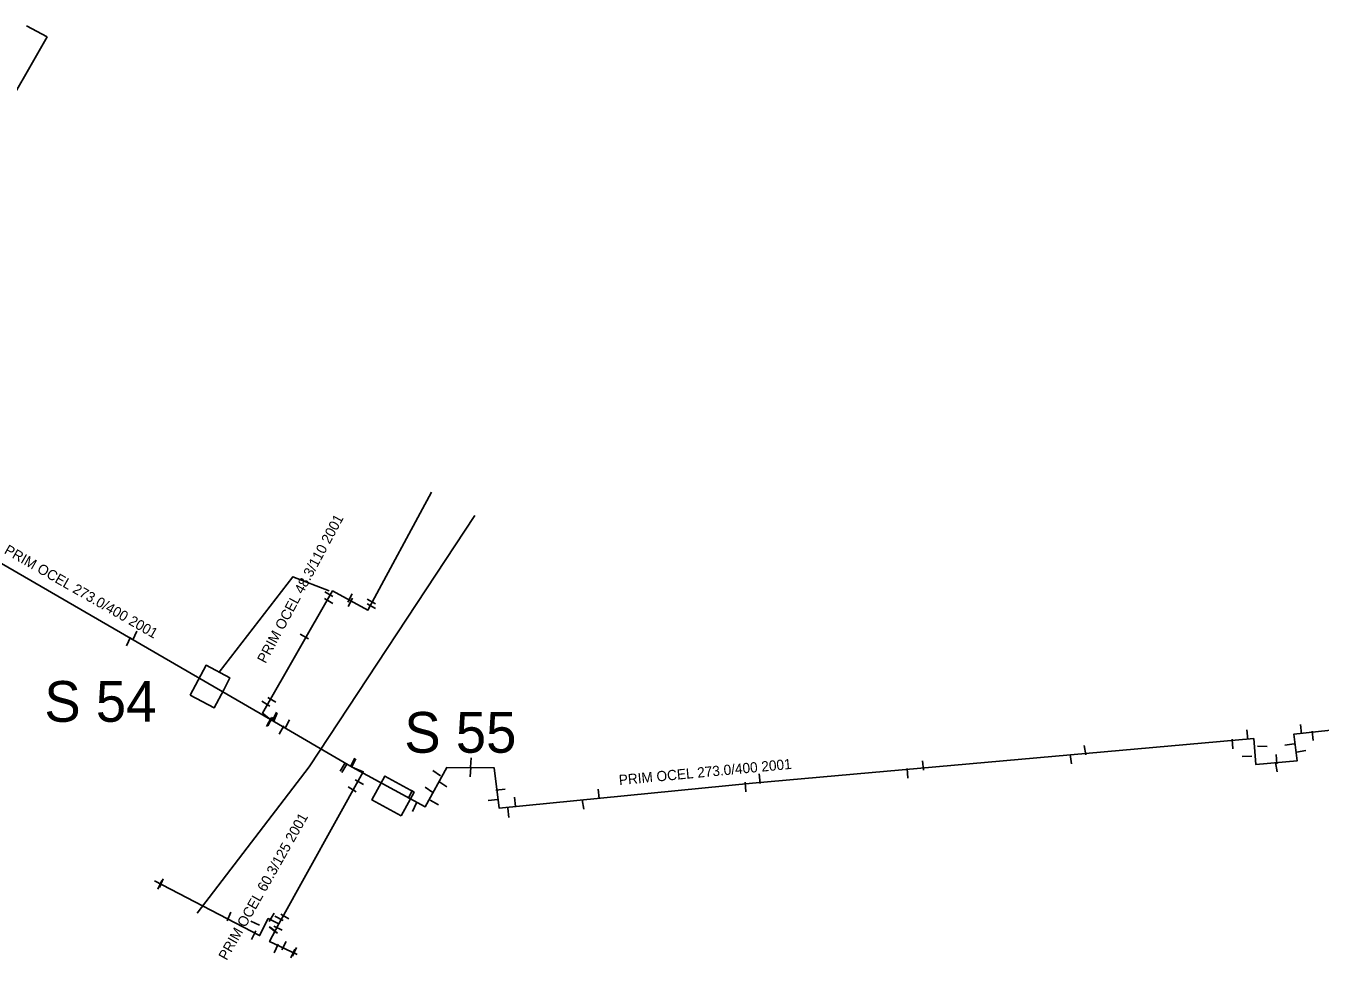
# Model space of a CAD drawing. Extents: x -642943 to -623314, y -1138561 to -1113539.
# Drawn here: x -642335.3 to -642240, y -1114485 to -1114416.3 of the extents above; entities that cross this region are included whole.
import ezdxf

# ---------------------------------------------------------------- set-up
doc = ezdxf.new("R2010")
doc.units = 0
for name, color, linetype in [('horkovod dimenze', 7, 'Continuous'), ('horkovod předisol', 7, 'Continuous'), ('horkovod sváry', 7, 'Continuous'), ('horkovod trasa', 7, 'Continuous'), ('horkovod zrušený', 7, 'Continuous'), ('horkovod číslo šachty', 7, 'Continuous')]:
    doc.layers.add(name, color=color, linetype=linetype)

# ---------------------------------------------------------------- blocks, each defined once
blk = doc.blocks.new('SPH')
at = {"layer": 'horkovod sváry'}
blk.add_line((0, -0.035), (0, 0.035), dxfattribs=at)

msp = doc.modelspace()

# ---------------------------------------------------------------- linework, layer by layer
at = {"layer": 'horkovod předisol'}
msp.add_line((-642311.275, -1114470.822), (-642317.299, -1114467.313), dxfattribs=at)
for points in [[(-642317.299, -1114467.313), (-642349.857, -1114448.448), (-642349.163, -1114446.91), (-642350.412, -1114445.977)], [(-642317.299, -1114467.313), (-642317.879, -1114466.834), (-642312.727, -1114457.853), (-642310.116, -1114459.253), (-642305.43, -1114450.586)], [(-642233.548, -1114467.487), (-642241.959, -1114468.39), (-642241.719, -1114470.343), (-642244.767, -1114470.621), (-642244.918, -1114468.717), (-642281.819, -1114471.99), (-642300.471, -1114473.836), (-642300.824, -1114470.879), (-642304.311, -1114470.841), (-642305.899, -1114473.739), (-642311.275, -1114470.822)], [(-642311.275, -1114470.822), (-642310.467, -1114471.162), (-642316.689, -1114482.351)], [(-642316.689, -1114482.351), (-642317.452, -1114481.967), (-642318.1, -1114483.211), (-642325.837, -1114479.183)], [(-642316.689, -1114482.351), (-642317.361, -1114483.66), (-642315.318, -1114484.605)]]:
    msp.add_lwpolyline(points, dxfattribs=at)
at = {"layer": 'horkovod trasa'}
msp.add_line((-642311.275, -1114470.822), (-642317.299, -1114467.313), dxfattribs=at)
for points in [[(-642317.299, -1114467.313), (-642349.857, -1114448.448), (-642349.163, -1114446.91), (-642350.412, -1114445.977)], [(-642317.299, -1114467.313), (-642317.879, -1114466.834), (-642312.727, -1114457.853), (-642310.116, -1114459.253), (-642305.43, -1114450.586)], [(-642233.548, -1114467.487), (-642241.959, -1114468.39), (-642241.719, -1114470.343), (-642244.767, -1114470.621), (-642244.918, -1114468.717), (-642281.819, -1114471.99), (-642300.471, -1114473.836), (-642300.824, -1114470.879), (-642304.311, -1114470.841), (-642305.899, -1114473.739), (-642311.275, -1114470.822)], [(-642311.275, -1114470.822), (-642310.467, -1114471.162), (-642316.689, -1114482.351)], [(-642316.689, -1114482.351), (-642317.452, -1114481.967), (-642318.1, -1114483.211), (-642325.837, -1114479.183)], [(-642316.689, -1114482.351), (-642317.361, -1114483.66), (-642315.318, -1114484.605)]]:
    msp.add_lwpolyline(points, dxfattribs=at)
at = {"layer": 'horkovod zrušený'}
for p, q in [((-642333.719, -1114417.07), (-642335.254, -1114416.26)), ((-642351.167, -1114447.304), (-642333.719, -1114417.07)), ((-642302.247, -1114452.304), (-642314.443, -1114470.785)), ((-642322.692, -1114481.558), (-642314.443, -1114470.785))]:
    msp.add_line(p, q, dxfattribs=at)
for points in [[(-642321.061, -1114463.832), (-642315.655, -1114456.81), (-642312.975, -1114457.831)], [(-642323.213, -1114465.523), (-642322.039, -1114463.316), (-642320.273, -1114464.255), (-642320.735, -1114465.124)], [(-642320.737, -1114465.128), (-642321.447, -1114466.462), (-642323.213, -1114465.523)], [(-642307.68, -1114474.407), (-642306.718, -1114472.654), (-642308.866, -1114471.475), (-642309.828, -1114473.228), (-642307.68, -1114474.407)]]:
    msp.add_lwpolyline(points, dxfattribs=at)

# ---------------------------------------------------------------- block references
at = {"layer": 'horkovod sváry'}
for p, xscale, yscale, rotation in [((-642313.001, -1114458.088), 9.999998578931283, 9.999998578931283, -120.46166251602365), ((-642311.43, -1114458.363), 10.000009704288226, 10.000009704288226, -27.095668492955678), ((-642313.011, -1114458.589), 9.999998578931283, 9.999998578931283, -120.46166251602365), ((-642311.425, -1114458.693), 10.000009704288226, 10.000009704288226, -27.095668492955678), ((-642309.872, -1114458.63), 9.999998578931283, 9.999998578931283, -120.46166251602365), ((-642309.869, -1114458.972), 9.999998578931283, 9.999998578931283, -120.46166251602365), ((-642327.287, -1114461.14), 10.000000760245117, 10.000000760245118, -24.424214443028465), ((-642314.796, -1114461.208), 9.999998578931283, 9.999998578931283, -120.46166251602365), ((-642327.747, -1114461.57), 9.999970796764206, 9.999970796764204, -23.401608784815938), ((-642317.197, -1114465.87), 9.999998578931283, 9.999998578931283, -120.46166251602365), ((-642317.637, -1114466.15), 10.000014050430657, 10.00001405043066, 59.228055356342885), ((-642316.997, -1114467.08), 9.999986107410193, 9.999986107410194, -24.942813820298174), ((-642316.937, -1114467.16), 9.999983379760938, 9.999983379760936, -23.96240770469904), ((-642317.417, -1114467.51), 9.999990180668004, 9.999990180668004, -28.17117343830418), ((-642317.317, -1114467.46), 10.000002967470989, 10.000002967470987, -27.68826968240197), ((-642316.477, -1114468.08), 9.999975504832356, 9.999975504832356, -28.062316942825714), ((-642316.057, -1114467.65), 10.000009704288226, 10.000009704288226, -27.095668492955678), ((-642241.447, -1114468.02), 9.999979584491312, 9.999979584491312, 6.1316765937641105), ((-642246.477, -1114469.12), 9.999996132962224, 9.999996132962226, 5.135127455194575), ((-642245.387, -1114468.43), 9.999994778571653, 9.999994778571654, 6.5713937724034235), ((-642240.577, -1114468.51), 9.999980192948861, 9.999980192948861, 6.514469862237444), ((-642257.327, -1114469.57), 10.000001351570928, 10.000001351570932, 10.089523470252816), ((-642244.287, -1114469.29), 10.000010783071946, 10.00001078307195, -90.61152736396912), ((-642242.277, -1114469.15), 10.000017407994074, 10.000017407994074, -83.20512119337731), ((-642241.417, -1114469.65), 9.999993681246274, 9.999993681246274, -80.9762188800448), ((-642311.977, -1114470.81), 9.999983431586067, 9.999983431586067, -31.63987333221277), ((-642311.857, -1114470.91), 10.000001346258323, 10.000001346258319, -30.916489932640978), ((-642311.247, -1114470.47), 9.999976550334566, 9.999976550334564, -26.565051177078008), ((-642311.177, -1114470.51), 10.000005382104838, 10.000005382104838, -26.18824021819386), ((-642302.547, -1114470.47), 10.000017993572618, 10.000017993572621, -5.752353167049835), ((-642269.257, -1114470.7), 10.000003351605, 10.000003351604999, 6.803217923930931), ((-642258.377, -1114470.23), 10.000012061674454, 10.000012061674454, 6.722072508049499), ((-642245.417, -1114470.03), 9.999985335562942, 9.999985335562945, -88.88468420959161), ((-642243.257, -1114470.82), 10.000012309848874, 10.000012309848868, 10.428436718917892), ((-642243.237, -1114470.23), 10.000001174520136, 10.000001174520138, 3.6138639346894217), ((-642305.057, -1114471.26), 9.999980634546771, 9.99998063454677, 55.87385535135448), ((-642302.567, -1114471.18), 9.999981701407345, 9.999981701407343, -4.170378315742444), ((-642281.287, -1114471.67), 10.000015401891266, 10.000015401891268, 5.440306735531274), ((-642270.407, -1114471.27), 10.00001845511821, 10.00001845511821, 5.000654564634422), ((-642311.287, -1114472.46), 10.000010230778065, 10.000010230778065, 57.506052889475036), ((-642310.757, -1114471.92), 10.000004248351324, 10.000004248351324, 59.83536285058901), ((-642306.997, -1114472.82), 10.000018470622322, 10.000018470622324, -26.19504200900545), ((-642305.627, -1114472.49), 9.99999889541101, 9.99999889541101, 53.59850998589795), ((-642304.607, -1114472.08), 10.00000860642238, 10.00000860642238, 56.595122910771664), ((-642300.357, -1114472.48), 9.999980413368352, 9.999980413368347, -84.54493330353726), ((-642293.137, -1114472.79), 9.999982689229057, 9.999982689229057, 6.126844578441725), ((-642282.327, -1114472.28), 10.000005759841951, 10.000005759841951, 5.470598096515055), ((-642306.697, -1114473.77), 10.000016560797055, 10.000016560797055, -24.41860593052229), ((-642305.227, -1114473.42), 10.000016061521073, 10.00001606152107, 59.328308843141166), ((-642300.917, -1114473.23), 9.999986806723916, 9.999986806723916, -84.23877963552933), ((-642299.287, -1114473.38), 9.999984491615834, 9.999984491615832, 5.946818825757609), ((-642294.287, -1114473.57), 9.999974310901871, 9.999974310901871, 8.706241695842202), ((-642299.787, -1114474.18), 9.999976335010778, 9.999976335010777, 4.440081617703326), ((-642325.437, -1114479.49), 9.99998276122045, 9.99998276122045, -23.67368167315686), ((-642325.327, -1114479.35), 10.000004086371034, 10.000004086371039, -23.99681188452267), ((-642320.347, -1114481.82), 10.000008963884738, 10.000008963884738, -24.18121328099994), ((-642317.207, -1114481.88), 10.000011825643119, 10.00001182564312, -30.372204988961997), ((-642316.657, -1114481.95), 10.000004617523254, 10.000004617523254, 62.22341636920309), ((-642316.237, -1114481.81), 10.000007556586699, 10.000007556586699, 58.793870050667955), ((-642318.417, -1114482.3), 10.000019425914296, 10.000019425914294, 63.76689465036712), ((-642318.527, -1114483.18), 10.000003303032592, 10.000003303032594, -25.680029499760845), ((-642317.127, -1114482.79), 10.00000078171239, 10.00000078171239, 51.67324509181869), ((-642317.057, -1114482.81), 9.999987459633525, 9.999987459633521, 50.63415215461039), ((-642316.737, -1114482.67), 10.00001177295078, 10.000011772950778, 63.737422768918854), ((-642316.877, -1114484.17), 9.999985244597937, 9.999985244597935, -26.246587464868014), ((-642316.307, -1114483.96), 10.000017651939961, 10.000017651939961, -26.680432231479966), ((-642315.657, -1114484.53), 10.000008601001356, 10.000008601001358, -25.159217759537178), ((-642315.527, -1114484.42), 10.000013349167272, 10.00001334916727, -23.328843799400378)]:
    msp.add_blockref('SPH', p, dxfattribs=dict(at, xscale=xscale, yscale=yscale, rotation=rotation))

# ---------------------------------------------------------------- texts
at = {"layer": 'horkovod dimenze'}
for s, rotation, p in [('PRIM OCEL 48.3/110 2001', 61.81454, (-642317.654, -1114463.237)), ('PRIM OCEL 273.0/400 2001', 330.30854, (-642336.955, -1114455.053)), ('PRIM OCEL 273.0/400 2001', 5.39926, (-642291.615, -1114472.144)), ('PRIM OCEL 60.3/125 2001', 60.49627, (-642320.515, -1114485.094))]:
    msp.add_text(s, height=0.75, rotation=rotation, dxfattribs=at).set_placement(p)
at = {"layer": 'horkovod číslo šachty'}
for s, p in [('S 54', (-642333.94, -1114467.481)), ('S 55', (-642307.443, -1114469.759))]:
    msp.add_text(s, height=3, dxfattribs=at).set_placement(p)

doc.saveas('drawing.dxf')
